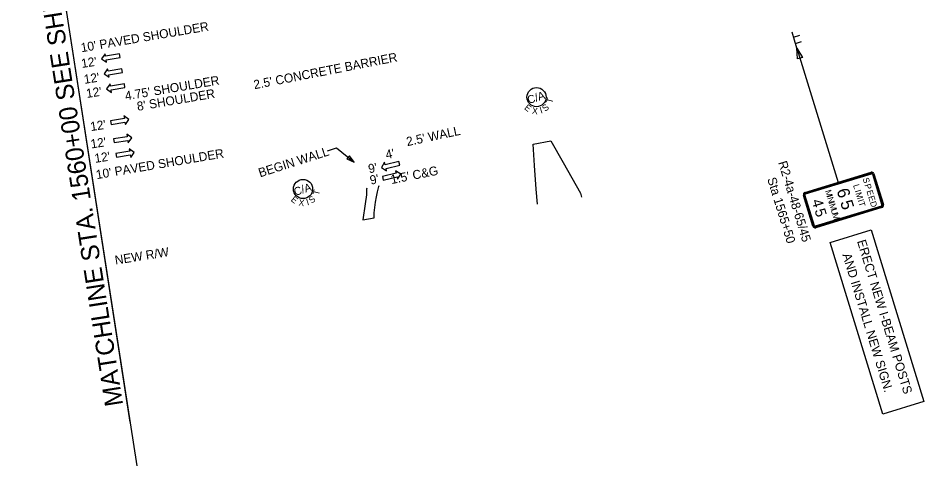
# Model space of a CAD drawing. Extents: x 1803351 to 1804929, y 1187729 to 1188936.
# Drawn here: x 1803351 to 1804059, y 1187729 to 1188078 of the extents above; entities that cross this region are included whole.
import ezdxf

# ---------------------------------------------------------------- set-up
doc = ezdxf.new("R2010")
doc.units = 0
for name, color, linetype in [('GIS ROW', 7, 'Continuous'), ('RD_EX_DV_Prop', 7, 'Continuous'), ('RD_EX_DV_Prop_txCode', 7, 'Continuous'), ('RD_EX_RW', 7, 'Continuous'), ('RD_PD_Final_LnLine', 7, 'Continuous'), ('RD_PD_Final_TX', 7, 'Continuous'), ('RD_SHT_MatchLine', 7, 'Continuous'), ('Survey Property', 7, 'Continuous'), ('Survey ROW', 7, 'Continuous')]:
    doc.layers.add(name, color=color, linetype=linetype)

# ---------------------------------------------------------------- blocks, each defined once
blk = doc.blocks.new('SARRW2')
at = {"layer": 'RD_PD_Final_LnLine'}
blk.add_lwpolyline([(-12, 1.2), (-12, -1.2), (-2.83, -1.2), (-2.83, -2.83), (0, 0), (-2.83, 2.83), (-2.83, 1.2)], close=True, dxfattribs=at)

msp = doc.modelspace()

# ---------------------------------------------------------------- linework, layer by layer
at = {"layer": 'GIS ROW'}
for centre in [(1803756, 1188016.41), (1803573.66, 1187944.73)]:
    msp.add_circle(centre, 7.5, dxfattribs=at)
at = {"layer": 'RD_EX_DV_Prop_txCode'}
msp.add_lwpolyline([(1803607.92, 1187968.32), (1803613.52, 1187965.7), (1803609.81, 1187970.65)], close=True, dxfattribs=at)
at = {"layer": 'RD_EX_RW'}
for points in [[(1803756.67, 1187932.99), (1803755.61, 1187944.65), (1803754.45, 1187963.17), (1803753.31, 1187979.74), (1803767.14, 1187982.23), (1803776.87, 1187965.36), (1803790.41, 1187941.56), (1803791.08, 1187938.38)], [(1803623.42, 1187945.3), (1803623.31, 1187944.67), (1803623.1, 1187940.18), (1803622.26, 1187933.17), (1803620.41, 1187920.8), (1803629.07, 1187922.17), (1803629.23, 1187926.09), (1803629.59, 1187930.26), (1803630.14, 1187934.42), (1803630.89, 1187938.54), (1803631.83, 1187942.62), (1803632.96, 1187946.66), (1803633.2, 1187947.37)]]:
    msp.add_lwpolyline(points, dxfattribs=at)
at = {"layer": 'RD_PD_Final_TX'}
for p, q in [((1803592.8, 1187974.5), (1803599.89, 1187976.76)), ((1803599.89, 1187976.76), (1803613.52, 1187965.7))]:
    msp.add_line(p, q, dxfattribs=at)
at = {"layer": 'RD_SHT_MatchLine'}
for p, q in [((1803357.33, 1188286.92), (1803443.72, 1187728.78)), ((1803359.07, 1188275.71), (1803438.45, 1187762.8))]:
    msp.add_line(p, q, dxfattribs=at)
at = {"layer": 'Survey Property'}
for p, q in [((1803959.39, 1188054.63), (1803955.56, 1188067.1)), ((1803956.77, 1188063.17), (1803961.54, 1188064.63)), ((1803958.24, 1188058.37), (1803963.01, 1188059.83)), ((1803959.39, 1188054.63), (1803991.49, 1187949.93)), ((1803965.68, 1187942.01), (1804017.31, 1187957.85)), ((1804019.56, 1187956.65), (1804026.94, 1187932.56)), ((1803971.87, 1187915.67), (1803964.49, 1187939.77)), ((1804025.75, 1187930.31), (1803974.12, 1187914.48)), ((1803985.37, 1187903.05), (1804017.51, 1187912.91)), ((1804017.51, 1187912.91), (1804058.56, 1187779.04)), ((1804026.42, 1187769.18), (1803985.37, 1187903.05)), ((1804058.56, 1187779.04), (1804026.42, 1187769.18))]:
    msp.add_line(p, q, dxfattribs=at)
msp.add_lwpolyline([(1803959.83, 1188046.19), (1803959.39, 1188054.63), (1803963.75, 1188047.39)], close=True, dxfattribs=at)
for points in [[(1803965.81, 1187941.58), (1804017.44, 1187957.42)], [(1803966.03, 1187940.87), (1804017.66, 1187956.7)], [(1804018.41, 1187956.3), (1804025.8, 1187932.21)], [(1804019.13, 1187956.52), (1804026.51, 1187932.43)], [(1803972.3, 1187915.8), (1803964.92, 1187939.9)], [(1803973.02, 1187916.02), (1803965.63, 1187940.12)], [(1804025.4, 1187931.46), (1803973.77, 1187915.63)], [(1804025.62, 1187930.74), (1803973.99, 1187914.91)]]:
    msp.add_lwpolyline(points, dxfattribs=at)
for centre, radius, start, end in [((1804017.83, 1187956.12), 1.8, 17.04793, 107.04793), ((1804017.83, 1187956.12), 1.35, 17.04793, 107.04793), ((1804017.83, 1187956.12), 0.6, 17.04793, 107.04793), ((1803966.21, 1187940.29), 1.8, 107.04793, 197.04793), ((1803966.21, 1187940.29), 1.35, 107.04793, 197.04793), ((1803966.21, 1187940.29), 0.6, 107.04793, 197.04793), ((1804025.22, 1187932.03), 0.6, 287.04793, 17.04793), ((1804025.22, 1187932.03), 1.35, 287.04793, 17.04793), ((1804025.22, 1187932.03), 1.8, 287.04793, 17.04793), ((1803973.6, 1187916.2), 1.8, 197.04793, 287.04793), ((1803973.6, 1187916.2), 1.35, 197.04793, 287.04793), ((1803973.6, 1187916.2), 0.6, 197.04793, 287.04793)]:
    msp.add_arc(centre, radius, start, end, dxfattribs=at)

# ---------------------------------------------------------------- block references
at = {"layer": 'RD_PD_Final_LnLine'}
for p, xscale, yscale, rotation in [((1803416.28, 1188046.41), 1.1999999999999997, 1.2000000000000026, -170.73306467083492), ((1803418.19, 1188034.67), 1.1999999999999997, 1.2000000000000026, -170.73306467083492), ((1803420.11, 1188022.92), 1.1999999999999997, 1.2000000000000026, -170.73306467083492), ((1803437.65, 1187998.9), 1.2, 1.2000000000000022, 9.266935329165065), ((1803439.98, 1187984.66), 1.2, 1.2000000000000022, 9.266935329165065), ((1803441.84, 1187973.26), 1.2, 1.2000000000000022, 9.266935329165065), ((1803634.82, 1187961.5), 1.2000000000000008, 1.2000000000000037, -167.0226491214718), ((1803650.02, 1187956.39), 1.2000000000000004, 1.2000000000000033, 12.977350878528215)]:
    msp.add_blockref('SARRW2', p, dxfattribs=dict(at, xscale=xscale, yscale=yscale, rotation=rotation))

# ---------------------------------------------------------------- texts
at = {"layer": 'GIS ROW'}
for s, height, rotation, p in [('C/A', 6.25, 17.67352, (1803749.93, 1188011.03)), ('T', 5, 75.85867, (1803768.35, 1188011.2)), ('E', 5, 320.88477, (1803746.03, 1188007.43)), ('X', 5, 353.31414, (1803752.3, 1188003.5)), ('I', 5, 17.47414, (1803759.39, 1188003.58)), ('S', 5, 39.46597, (1803762.82, 1188004.86)), ('C/A', 6.25, 17.67352, (1803567.59, 1187939.35)), ('T', 5, 75.85867, (1803586.01, 1187939.52)), ('E', 5, 320.88477, (1803563.69, 1187935.76)), ('X', 5, 353.31414, (1803569.96, 1187931.82)), ('I', 5, 17.47414, (1803577.05, 1187931.9)), ('S', 5, 39.46597, (1803580.48, 1187933.18))]:
    msp.add_text(s, height=height, rotation=rotation, dxfattribs=at).set_placement(p)
at = {"layer": 'RD_EX_DV_Prop'}
msp.add_text('MATCHLINE STA. 1560+00 SEE SHEET NO. SN47', height=14.1726, rotation=98.91974, dxfattribs=at).set_placement((1803433.14, 1187776.36))
at = {"layer": 'RD_PD_Final_TX'}
for s, rotation, p in [("10' PAVED SHOULDER", 9.65303, (1803400.66, 1188051.43)), ("2.5' CONCRETE BARRIER", 11.01867, (1803535.71, 1188022.57)), ("12'", 8.64011, (1803400.94, 1188039.16)), ("12'", 8.64011, (1803402.97, 1188026.76)), ("4.75' SHOULDER", 9.62516, (1803435.15, 1188013.85)), ("12'", 8.64011, (1803404.76, 1188015.75)), ("8' SHOULDER", 9.62516, (1803444.51, 1188005.69)), ("12'", 8.64011, (1803408.01, 1187989.91)), ("2.5' WALL", 12.01625, (1803655.08, 1187978.15)), ("12'", 8.64011, (1803408.26, 1187976.34)), ("12'", 8.64011, (1803411.29, 1187965.12)), ("10' PAVED SHOULDER", 9.65303, (1803412.51, 1187952.41)), ('BEGIN WALL', 17.67352, (1803540.1, 1187953.8)), ("4'", 12.29293, (1803638.82, 1187967.96)), ("9'", 12.29293, (1803625.37, 1187956.91)), ("9'", 12.29293, (1803626.64, 1187948.07)), ("1.5' C&G", 11.37312, (1803642.82, 1187948.57))]:
    msp.add_text(s, height=7, rotation=rotation, dxfattribs=at).set_placement(p)
at = {"layer": 'Survey Property'}
for s, height, rotation, p in [('R2-4a-48-65/45', 7, 287.04801, (1803944.67, 1187965.42)), ('Sta 1565+50', 7, 287.04801, (1803936.14, 1187952.66)), ('S', 4.8, 287.04793, (1804010.68, 1187952.84)), ('P', 4.8, 287.04793, (1804012.18, 1187947.96)), ('M', 4.8, 287.04793, (1803981.3, 1187943.25)), ('6', 9.6, 287.04793, (1803990.27, 1187943.69)), ('L', 4.8, 287.04793, (1804003.18, 1187947.64)), ('I', 4.8, 287.04793, (1804004.5, 1187943.33)), ('M', 4.8, 287.04793, (1804005.1, 1187941.36)), ('E', 4.8, 287.04793, (1804013.67, 1187943.09)), ('4', 8.4, 287.04793, (1803970.81, 1187935.53)), ('I', 4.8, 287.04793, (1803982.51, 1187939.31)), ('N', 4.8, 287.04793, (1803983.01, 1187937.7)), ('I', 4.8, 287.04793, (1803984.07, 1187934.22)), ('5', 9.6, 287.04793, (1803993.09, 1187934.48)), ('I', 4.8, 287.04793, (1804006.76, 1187935.94)), ('T', 4.8, 287.04793, (1804007.3, 1187934.21)), ('E', 4.8, 287.04793, (1804015.01, 1187938.74)), ('D', 4.8, 287.04793, (1804016.34, 1187934.4)), ('5', 8.4, 287.04793, (1803973.08, 1187928.12)), ('M', 4.8, 287.04793, (1803984.57, 1187932.61)), ('U', 4.8, 287.04793, (1803985.78, 1187928.67)), ('M', 4.8, 287.04793, (1803986.84, 1187925.19)), ('ERECT NEW I-BEAM POSTS', 6.9998, 287.04801, (1804006.27, 1187903.99)), ('AND INSTALL NEW SIGN.', 6.9998, 287.04801, (1803994.84, 1187893.48))]:
    msp.add_text(s, height=height, rotation=rotation, dxfattribs=at).set_placement(p)
at = {"layer": 'Survey ROW'}
msp.add_text('NEW R/W', height=7, rotation=9.10296, dxfattribs=at).set_placement((1803427.21, 1187885.73))

doc.saveas('drawing.dxf')
